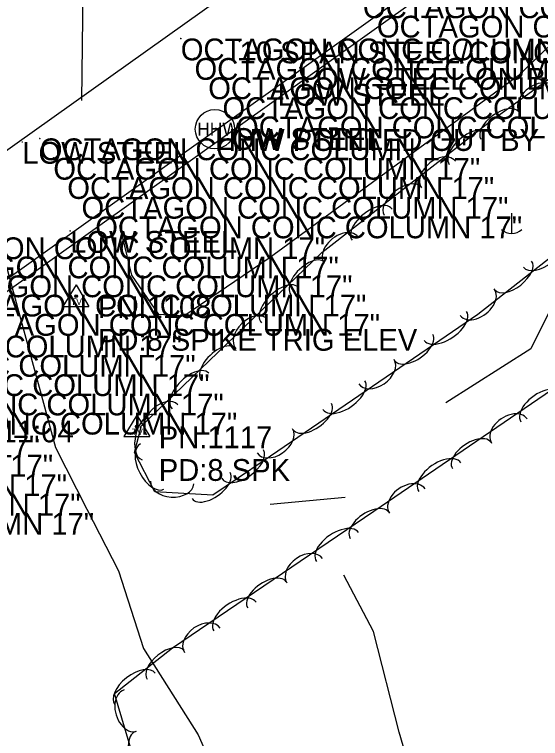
# Model space of a CAD drawing. Extents: x 1451369 to 1458940, y 1868647 to 1875095.
# Drawn here: x 1454437.4 to 1454557.9, y 1871458.6 to 1871624.7 of the extents above; entities that cross this region are included whole.
import ezdxf

# ---------------------------------------------------------------- set-up
doc = ezdxf.new("R2010")
doc.units = 0
for name, color, linetype in [('E_Const Align', 7, 'Continuous'), ('E_Existing_ROW', 7, 'Continuous'), ('E_Proposed ROW and Easements', 7, 'Continuous'), ('E_Quarter Section Line', 7, 'Continuous'), ('E_ROW Point Number', 7, 'Continuous'), ('E_Station Offset', 7, 'Continuous'), ('E_Tract Residual', 7, 'Continuous'), ('R_Proposed Const Limits', 7, 'Continuous'), ('S_EXIST_ROW', 7, 'Continuous'), ('S_HIST_HIGH_WATER_ANNOT', 7, 'Continuous'), ('S_MISC_STRUCTURES_ANNOT', 7, 'Continuous'), ('S_SECONDARY_CTL_ANNOT', 7, 'Continuous'), ('S_SURVEY_TEXT_ANNOT', 7, 'Continuous'), ('S_TRAILS', 7, 'Continuous')]:
    doc.layers.add(name, color=color, linetype=linetype)

msp = doc.modelspace()

# ---------------------------------------------------------------- linework, layer by layer
at = {"layer": 'E_Const Align'}
msp.add_line((1454551.24, 1871579.14), (1454551.24, 1871574.41), dxfattribs=at)
msp.add_arc((1454551.3, 1871577.84), 3.41, 226.3972, 313.6028, dxfattribs=at)
at = {"layer": 'E_Existing_ROW'}
for p, q in [((1454539.16, 1871667.36), (1454213.66, 1871435.13)), ((1454227.64, 1871415.7), (1454553.13, 1871647.85))]:
    msp.add_line(p, q, dxfattribs=at)
at = {"layer": 'E_Proposed ROW and Easements'}
for points in [[(1454520.42, 1871624.4), (1454520.42, 1871624.45), (1454520.42, 1871624.4), (1454520.37, 1871624.4), (1454520.42, 1871624.4), (1454520.42, 1871624.35), (1454520.42, 1871624.4), (1454520.47, 1871624.4)], [(1454475.47, 1871619.17), (1454475.47, 1871619.22), (1454475.47, 1871619.17), (1454475.42, 1871619.17), (1454475.47, 1871619.17), (1454475.47, 1871619.12), (1454475.47, 1871619.17), (1454475.52, 1871619.17)], [(1454488.95, 1871618.48), (1454488.95, 1871618.53), (1454488.95, 1871618.48), (1454488.9, 1871618.48), (1454488.95, 1871618.48), (1454488.95, 1871618.43), (1454488.95, 1871618.48), (1454489, 1871618.48)], [(1454478.62, 1871614.7), (1454478.62, 1871614.75), (1454478.62, 1871614.7), (1454478.57, 1871614.7), (1454478.62, 1871614.7), (1454478.62, 1871614.65), (1454478.62, 1871614.7), (1454478.67, 1871614.7)], [(1454502.72, 1871612.44), (1454502.72, 1871612.49), (1454502.72, 1871612.44), (1454502.67, 1871612.44), (1454502.72, 1871612.44), (1454502.72, 1871612.39), (1454502.72, 1871612.44), (1454502.77, 1871612.44)], [(1454481.76, 1871610.26), (1454481.76, 1871610.31), (1454481.76, 1871610.26), (1454481.71, 1871610.26), (1454481.76, 1871610.26), (1454481.76, 1871610.21), (1454481.76, 1871610.26), (1454481.81, 1871610.26)], [(1454497.65, 1871608.76), (1454497.65, 1871608.81), (1454497.65, 1871608.76), (1454497.6, 1871608.76), (1454497.65, 1871608.76), (1454497.65, 1871608.71), (1454497.65, 1871608.76), (1454497.7, 1871608.76)], [(1454485.02, 1871605.7), (1454485.02, 1871605.75), (1454485.02, 1871605.7), (1454484.97, 1871605.7), (1454485.02, 1871605.7), (1454485.02, 1871605.65), (1454485.02, 1871605.7), (1454485.07, 1871605.7)], [(1454488.14, 1871601.28), (1454488.14, 1871601.33), (1454488.14, 1871601.28), (1454488.09, 1871601.28), (1454488.14, 1871601.28), (1454488.14, 1871601.23), (1454488.14, 1871601.28), (1454488.19, 1871601.28)], [(1454483.52, 1871598.62), (1454483.52, 1871598.67), (1454483.52, 1871598.62), (1454483.47, 1871598.62), (1454483.52, 1871598.62), (1454483.52, 1871598.57), (1454483.52, 1871598.62), (1454483.57, 1871598.62)], [(1454439.14, 1871595.45), (1454439.14, 1871595.5), (1454439.14, 1871595.45), (1454439.09, 1871595.45), (1454439.14, 1871595.45), (1454439.14, 1871595.4), (1454439.14, 1871595.45), (1454439.19, 1871595.45)], [(1454443.16, 1871596.26), (1454443.16, 1871596.31), (1454443.16, 1871596.26), (1454443.11, 1871596.26), (1454443.16, 1871596.26), (1454443.16, 1871596.21), (1454443.16, 1871596.26), (1454443.21, 1871596.26)], [(1454446.26, 1871591.8), (1454446.26, 1871591.85), (1454446.26, 1871591.8), (1454446.21, 1871591.8), (1454446.26, 1871591.8), (1454446.26, 1871591.75), (1454446.26, 1871591.8), (1454446.31, 1871591.8)], [(1454449.46, 1871587.38), (1454449.46, 1871587.43), (1454449.46, 1871587.38), (1454449.41, 1871587.38), (1454449.46, 1871587.38), (1454449.46, 1871587.33), (1454449.46, 1871587.38), (1454449.51, 1871587.38)], [(1454452.72, 1871582.85), (1454452.72, 1871582.9), (1454452.72, 1871582.85), (1454452.67, 1871582.85), (1454452.72, 1871582.85), (1454452.72, 1871582.8), (1454452.72, 1871582.85), (1454452.77, 1871582.85)], [(1454455.87, 1871578.35), (1454455.87, 1871578.4), (1454455.87, 1871578.35), (1454455.82, 1871578.35), (1454455.87, 1871578.35), (1454455.87, 1871578.3), (1454455.87, 1871578.35), (1454455.92, 1871578.35)], [(1454450.12, 1871575.03), (1454450.12, 1871575.08), (1454450.12, 1871575.03), (1454450.07, 1871575.03), (1454450.12, 1871575.03), (1454450.12, 1871574.98), (1454450.12, 1871575.03), (1454450.17, 1871575.03)]]:
    msp.add_lwpolyline(points, dxfattribs=at)
at = {"layer": 'E_Quarter Section Line'}
msp.add_line((1454551.64, 1871643.91), (1454234.22, 1871417.39), dxfattribs=at)
at = {"layer": 'E_ROW Point Number'}
for points in [[(1454466.05, 1871529.96), (1454507.82, 1871570.12), (1454546.16, 1871599.98), (1454595.25, 1871635.71), (1454622.47, 1871655.87), (1454630.45, 1871654.58), (1454632.33, 1871647.54), (1454628.1, 1871629.79), (1454610.02, 1871609.22), (1454579.17, 1871583.81), (1454543.54, 1871555.84), (1454533.41, 1871548.93), (1454494.55, 1871522.4), (1454482.82, 1871514.43), (1454469.55, 1871515.19), (1454464.89, 1871524.19), (1454466.39, 1871530.13)], [(1454479.99, 1871402.54), (1454460.24, 1871468.96), (1454473.6, 1871479.41), (1454519.69, 1871510.73), (1454565.25, 1871541.9), (1454579.31, 1871534.81), (1454586.65, 1871522.9), (1454587.34, 1871467.45), (1454611.35, 1871460.55), (1454622.55, 1871447.83)]]:
    msp.add_lwpolyline(points, dxfattribs=at)
for centre, major_axis, ratio, start_param, end_param in [((1454557.06, 1871605.07), (-3.98, -2.95), 0.661859, 3.128451, 6.270044), ((1454548.59, 1871599.22), (-4.31, -3.16), 0.522222, 3.133582, 6.275174), ((1454541.62, 1871593.85), (-4.56, -3.64), 0.533376, 3.120046, 6.261639), ((1454534.51, 1871587.99), (-3.82, -3.12), 0.664282, 3.107212, 6.248805), ((1454526.28, 1871581.9), (-4.16, -3.31), 0.524289, 3.120695, 6.262287), ((1454519.32, 1871576.48), (-4.56, -3.64), 0.533376, 3.120046, 6.261639), ((1454512.2, 1871570.62), (-3.82, -3.12), 0.664282, 3.107212, 6.248805), ((1454558.65, 1871570.31), (4.61, 3.63), 0.530655, 3.139113, 6.280705), ((1454504.58, 1871564.17), (-3.85, -3.71), 0.521329, 3.137517, 6.27911), ((1454551.68, 1871564.83), (4.2, 3.31), 0.521606, 3.139187, 6.280779), ((1454498.19, 1871558.03), (-4.22, -4.08), 0.530373, 3.137392, 6.278985), ((1454543.42, 1871558.67), (3.89, 3.07), 0.661107, 3.137649, 6.279242), ((1454536.12, 1871553.25), (4.83, 3.33), 0.531431, 3.134118, 6.275711), ((1454491.69, 1871551.43), (-3.56, -3.45), 0.660751, 3.134917, 6.276509), ((1454528.87, 1871548.31), (4.34, 3.05), 0.526428, 3.115106, 6.256699), ((1454484.09, 1871544.47), (-3.85, -3.71), 0.521329, 3.137517, 6.27911), ((1454520.31, 1871542.77), (3.98, 2.89), 0.666854, 3.097882, 6.239474), ((1454477.7, 1871538.33), (-4.22, -4.08), 0.530373, 3.137392, 6.278985), ((1454512.86, 1871537.38), (4.76, 3.35), 0.535548, 3.114281, 6.255874), ((1454558.28, 1871534.56), (-4.84, -3.31), 0.5509, 3.141364, 6.282957), ((1454471.2, 1871531.73), (-3.56, -3.45), 0.660751, 3.134917, 6.276509), ((1454505.61, 1871532.43), (4.34, 3.05), 0.526428, 3.115106, 6.256699), ((1454467.91, 1871527.74), (-1.31, -5.18), 0.525779, 3.141593, 6.283185), ((1454550.8, 1871529.13), (-4.08, -2.79), 0.686333, 3.141217, 6.28281), ((1454497.04, 1871526.89), (3.98, 2.89), 0.666854, 3.097882, 6.239474), ((1454542.16, 1871523.54), (-4.41, -3.01), 0.541506, 3.141371, 6.282964), ((1454468.92, 1871521.01), (2.7, -5.21), 0.547926, 3.141593, 6.283185), ((1454489.64, 1871521.54), (4.72, 3.34), 0.538617, 3.10563, 6.247222), ((1454534.85, 1871518.54), (-4.84, -3.31), 0.5509, 3.141364, 6.282957), ((1454482.41, 1871516.63), (4.3, 3.04), 0.529455, 3.106724, 6.248317), ((1454473.49, 1871517.32), (4.95, -0.27), 0.674732, 3.137206, 6.278798), ((1454527.37, 1871513.1), (-4.08, -2.79), 0.686333, 3.141217, 6.28281), ((1454518.72, 1871507.51), (-4.42, -3), 0.541168, 3.141425, 6.283018), ((1454511.39, 1871502.53), (-4.85, -3.3), 0.550556, 3.141419, 6.283012), ((1454503.89, 1871497.12), (-4.09, -2.78), 0.685905, 3.141309, 6.282901), ((1454495.23, 1871491.55), (-4.42, -3), 0.541168, 3.141425, 6.283018), ((1454487.9, 1871486.57), (-4.85, -3.3), 0.550556, 3.141419, 6.283012), ((1454480.4, 1871481.15), (-4.09, -2.78), 0.685905, 3.141309, 6.282901), ((1454472, 1871475.47), (-4.21, -3.29), 0.540874, 3.141717, 6.283309), ((1454465.01, 1871470), (-4.62, -3.61), 0.550257, 3.141721, 6.283313), ((1454463.9, 1871465), (1.41, -4.75), 0.685972, 3.142537, 6.28413), ((1454466.58, 1871455.06), (1.52, -5.12), 0.541221, 3.14215, 6.283743)]:
    msp.add_ellipse(centre, major_axis=major_axis, ratio=ratio, start_param=start_param, end_param=end_param, dxfattribs=at)
at = {"layer": 'E_Station Offset'}
for p, q in [((1454451.47, 1871562.67), (1454448.46, 1871557.71)), ((1454451.47, 1871562.67), (1454454.41, 1871557.71)), ((1454448.46, 1871557.71), (1454454.41, 1871557.71)), ((1454465.42, 1871532.81), (1454462.41, 1871527.86)), ((1454465.42, 1871532.81), (1454468.37, 1871527.86)), ((1454462.41, 1871527.86), (1454468.37, 1871527.86))]:
    msp.add_line(p, q, dxfattribs=at)
for centre, radius in [((1454451.47, 1871560.06), 0.311), ((1454451.47, 1871560.06), 0.183), ((1454451.47, 1871560.06), 0.103), ((1454465.42, 1871530.2), 0.311), ((1454465.42, 1871530.2), 0.183), ((1454465.42, 1871530.2), 0.103)]:
    msp.add_circle(centre, radius, dxfattribs=at)
at = {"layer": 'E_Tract Residual'}
msp.add_lwpolyline([(1454435.49, 1871566.79), (1454439.25, 1871552.99), (1454443, 1871539.18), (1454446.75, 1871525.37), (1454453.97, 1871511.23), (1454461.19, 1871497.08), (1454466.96, 1871479.27), (1454479.45, 1871459.48), (1454487.96, 1871440.08)], dxfattribs=at)
at = {"layer": 'R_Proposed Const Limits'}
msp.add_circle((1454483.3, 1871598.39), 4.5, dxfattribs=at)
at = {"layer": 'S_EXIST_ROW'}
for points in [[(1454637.64, 1871635.17), (1454625.86, 1871621.8), (1454614.08, 1871608.44), (1454602.3, 1871595.08), (1454590.52, 1871581.71), (1454579.84, 1871573.65), (1454569.16, 1871565.58), (1454560.65, 1871558.01), (1454555.73, 1871548.02), (1454536.22, 1871535.62)], [(1454513.13, 1871513.86), (1454495.95, 1871512.28)], [(1454562.7, 1871387.08), (1454548.13, 1871404.98), (1454535.85, 1871424.34), (1454530.7, 1871442.21), (1454525.54, 1871460.07), (1454519.63, 1871483.17), (1454512.82, 1871496.11)]]:
    msp.add_lwpolyline(points, dxfattribs=at)
at = {"layer": 'S_TRAILS'}
for points in [[(1454452.76, 1871604.94), (1454453.07, 1871630.27), (1454458.72, 1871654.07), (1454466.48, 1871667.98), (1454475.78, 1871674.76), (1454498.57, 1871690.32), (1454531.15, 1871712.06), (1454574.69, 1871738.84), (1454607.46, 1871754.31), (1454634.61, 1871765.2), (1454664.57, 1871773.03), (1454675.34, 1871772.51), (1454679.89, 1871771.22)], [(1454633.14, 1871666.5), (1454620.4, 1871666.11), (1454609.48, 1871660.03), (1454584.95, 1871641.61), (1454552.82, 1871610.6), (1454495.73, 1871568.82), (1454476.2, 1871555.5), (1454470.45, 1871555.85), (1454464.28, 1871564.89), (1454461.53, 1871576.31)]]:
    msp.add_lwpolyline(points, dxfattribs=at)

# ---------------------------------------------------------------- texts
at = {"layer": 'E_Station Offset'}
for p in [(1454450.26, 1871558.05), (1454464.22, 1871528.19)]:
    msp.add_text('TV', height=1.5, rotation=360, dxfattribs=at).set_placement(p)
at = {"layer": 'R_Proposed Const Limits'}
msp.add_text('HHW', height=3, rotation=360, dxfattribs=at).set_placement((1454479.21, 1871596.89))
at = {"layer": 'S_HIST_HIGH_WATER_ANNOT'}
msp.add_text('HHW POINTED OUT BY PROPERTY OWN ELEV:176.57', height=5, dxfattribs=at).set_placement((1454483.3, 1871593.39))
at = {"layer": 'S_MISC_STRUCTURES_ANNOT'}
for s, p in [('OCTAGON CONC COLUMN 17"', (1454517.22, 1871623.84)), ('OCTAGON CONC COLUMN 17"', (1454520.42, 1871619.4)), ('OCTAGON CONC COLUMN 17"', (1454475.47, 1871614.17)), ('OCTAGON CONC COLUMN 17"', (1454478.62, 1871609.7)), ('OCTAGON CONC COLUMN 17"', (1454481.76, 1871605.26)), ('LOW STEEL', (1454497.65, 1871603.76)), ('OCTAGON CONC COLUMN 17"', (1454485.02, 1871600.7)), ('OCTAGON CONC COLUMN 17"', (1454488.14, 1871596.28)), ('LOW STEEL', (1454483.52, 1871593.62)), ('OCTAGON CONC COLUMN 17"', (1454443.16, 1871591.26)), ('LOW STEEL', (1454439.14, 1871590.45)), ('OCTAGON CONC COLUMN 17"', (1454446.26, 1871586.8)), ('OCTAGON CONC COLUMN 17"', (1454449.46, 1871582.38)), ('OCTAGON CONC COLUMN 17"', (1454452.72, 1871577.85)), ('OCTAGON CONC COLUMN 17"', (1454455.87, 1871573.35)), ('LOW STEEL', (1454450.12, 1871570.03)), ('OCTAGON CONC COLUMN 17"', (1454410.69, 1871568.56)), ('OCTAGON CONC COLUMN 17"', (1454413.85, 1871564.17)), ('OCTAGON CONC COLUMN 17"', (1454416.98, 1871559.83)), ('OCTAGON CONC COLUMN 17"', (1454420.15, 1871555.41)), ('OCTAGON CONC COLUMN 17"', (1454423.29, 1871550.99)), ('OCTAGON CONC COLUMN 17"', (1454377.9, 1871546.02)), ('OCTAGON CONC COLUMN 17"', (1454381.03, 1871541.59)), ('OCTAGON CONC COLUMN 17"', (1454384.22, 1871537.16)), ('OCTAGON CONC COLUMN 17"', (1454387.47, 1871532.73)), ('OCTAGON CONC COLUMN 17"', (1454390.57, 1871528.33)), ('LOW STEEL 09/18/2014 10:11:04', (1454349.45, 1871526.54)), ('OCTAGON CONC COLUMN 17"', (1454345.22, 1871523.1)), ('OCTAGON CONC COLUMN 17"', (1454348.37, 1871518.69)), ('OCTAGON CONC COLUMN 17"', (1454351.55, 1871514.2)), ('OCTAGON CONC COLUMN 17"', (1454354.66, 1871509.74)), ('OCTAGON CONC COLUMN 17"', (1454357.77, 1871505.37))]:
    msp.add_text(s, height=5, dxfattribs=at).set_placement(p)
at = {"layer": 'S_SECONDARY_CTL_ANNOT'}
for s, p in [('PN:1108', (1454456.47, 1871555.06)), ('PD:8 SPIKE TRIG ELEV', (1454456.47, 1871547.56)), ('PN:1117', (1454470.42, 1871525.2)), ('PD:8 SPK', (1454470.42, 1871517.7))]:
    msp.add_text(s, height=5, dxfattribs=at).set_placement(p)
at = {"layer": 'S_SURVEY_TEXT_ANNOT'}
for s, p in [('10 SPAN STEEL/CONC BR OCTAGON COL 17"', (1454488.95, 1871613.48)), ('LOW STEEL ON BR', (1454502.72, 1871607.44))]:
    msp.add_text(s, height=5, dxfattribs=at).set_placement(p)

doc.saveas('drawing.dxf')
